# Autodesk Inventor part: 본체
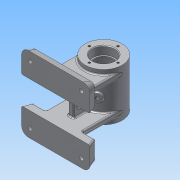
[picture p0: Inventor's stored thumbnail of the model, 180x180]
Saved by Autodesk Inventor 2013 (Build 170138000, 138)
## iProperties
Created: 2016-07
Part Number: 본체
Material: 알루미늄 6061
Document SubType Name: Modeling
Designer: Administrator
Density: 2.71 g/cm^3
Mass: 499.721 g
Surface Area: 539.152 cm^2
Volume: 184.399 cm^3
Author: Administrator
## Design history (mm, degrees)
sketch "스케치1"
  geometry: C1 r 27 at (0, 0); 1 further point
  constraints: 1 centre point, 1 coincident
  dimensions: "d0" = 54 diameter of C1
extrude "돌출1" new body sketch "스케치1" stored distance "d1" = 70; taper "d2" = 0 deg
node "작업 평면1"
node "작업 평면2"
sketch "스케치7"
  geometry: L1 (-40, 45)-(-50, 45); L2 (40, 45)-(50, 45); L3 (-27, -35)-(-27, 35) reference; L4 (27, -35)-(27, 35) reference; L5 (-40, 45)-(-40, 55); L6 (40, 45)-(40, 55); L7 (-40, 55)-(40, 55); L8 (-50, 45)-(-50, 20); L9 (-50, 20)-(50, 20); L10 (50, 20)-(50, 45); A1 r 10 centre (40, 45) between (50, 45) and (40, 55); A2 r 10 centre (-40, 45) between (-40, 55) and (-50, 45); 1 further point
  constraints: 16 end point, 4 point on circle, 3 parallel, 2 centre point, 2 tangent, 1 collinear, 1 horizontal, 1 perpendicular
  dimensions: "d51" = 20 diameter of A1; "d52" = 20 diameter of A2; "d53" = 50 horizontal distance of point (0, 0) L1.end; "d54" = 50 horizontal distance of point (0, 0) L2.end; "d55" = 55 vertical distance of point (0, 0) L5.end; "d56" = 55 vertical distance of point (0, 0) L6.end; "d57" = 20 distance from line of point (0, 0) L9
extrude "돌출5" join sketch "스케치7" distance "d58" = 12; taper "d59" = -20 deg
sketch "스케치8"
  geometry: L1 (-40, -55)-(40, -55) reference; L2 (-45.632, -45)-(-45.632, -24.368) reference; L3 (-45.632, -24.368)-(45.632, -24.368) reference; L4 (45.632, -24.368)-(45.632, -45) reference; L5 (40, -50.632)-(-40, -50.632) reference; L6 (-50, -20)-(-50, -45) reference; L7 (50, -45)-(50, -20) reference; A1 r 5.632 centre (40, -45) between (40, -50.632) and (45.632, -45) reference; A2 r 5.632 centre (-40, -45) between (-45.632, -45) and (-40, -50.632) reference; 3 further points
  dimensions: "d60" = 12.5 distance from line of L1 point (-37.8, -42.5); "d61" = 12.2 distance from line of L6 point (-37.8, -42.5); "d62" = 12.5 distance from line of L1 point (37.5, -42.5); "d63" = 12.5 distance from line of L7 point (37.5, -42.5)
hole "구멍2" sketch "스케치8" at (-37.8, -42.5), (37.5, -42.5) diameter "d64" = 6; stored, may be unused: countersink angle "d68" = 90 deg, drill point angle "d70" = 118 deg; dims "d65" = 6, "d66" = 10, "d67" = 4, "d69" = 8
sketch "스케치9"
  geometry: L1 (27, -35)-(-27, -35) reference; L2 (-27, -35)-(-27, 35) reference; L3 (-27, 35)-(27, 35) reference; L4 (27, 35)-(27, -35) reference; L5 (-70, 55)-(-58, 50.632) reference; L6 (-58, 50.632)-(-58, 24.368) reference; L7 (-58, 24.368)-(-70, 20) reference; L8 (-70, 20)-(-70, 55) reference; L9 (-58, 24.368)-(-58, 20); L10 (-58, 20)-(-70, 20); 1 further point
  constraints: 4 end point, 1 parallel, 1 perpendicular
extrude "돌출6" join sketch "스케치9" stored distance "d71" = 12; taper "d72" = 0 deg
sketch "스케치10"
  geometry: L1 (-45.632, -20)-(45.632, -20) reference; L2 (-27, -20)-(27, -20); L3 (27, -20)-(27, -28); L4 (27, -28)-(-27, -28); L5 (-27, -28)-(-27, -20); 3 further points
  constraints: 8 end point, 2 midpoint, 2 parallel, 1 coincident, 1 horizontal, 1 perpendicular, 1 point on line
  dimensions: "d73" = 54 distance of L3.end L4.end; "d74" = 8 distance of L2.end L3.end
extrude "돌출7" join sketch "스케치10" stored distance "d75" = 12; taper "d76" = 0 deg
fillet "모깎기6" dims "d77" = 2
fillet "모깎기7" dims "d78" = 2
fillet "모깎기8" dims "d79" = 2
fillet "모깎기9" dims "d80" = 2
sketch "스케치11"
  geometry: L1 (27, 35)-(27, -35) reference; L2 (27, -35)-(-27, -35) reference; L3 (-27, -35)-(-27, -28) reference; L4 (-27, -28)-(-56, -28) reference; L5 (-58, -30)-(-58, -49.232) reference; L6 (-59.316, -51.111)-(-70, -55) reference; L7 (-70, -55)-(-70, -20) reference; L8 (-70, -20)-(-27, -20) reference; L9 (-27, -20)-(-27, 20) reference; L10 (-27, 20)-(-70, 20) reference; L11 (-70, 20)-(-70, 55) reference; L12 (-70, 55)-(-59.316, 51.111) reference; L13 (-58, 49.232)-(-58, 30) reference; L14 (-56, 28)-(-27, 28) reference; L15 (-27, 28)-(-27, 35) reference; L16 (-27, 35)-(27, 35) reference; L17 (-48, 9.983)-(-48, -9.983); A1 r 2 centre (-56, -30) between (-56, -28) and (-58, -30) reference; A2 r 2 centre (-60, -49.232) between (-59.316, -51.111) and (-58, -49.232) reference; A3 r 2 centre (-60, 49.232) between (-58, 49.232) and (-59.316, 51.111) reference; A4 r 2 centre (-56, 30) between (-58, 30) and (-56, 28) reference; 1 further point
  constraints: 2 end point, 1 perpendicular
  dimensions: "d81" = 21 distance between parallel lines of L17 L9
feature "리브2" sketch "스케치11" dims "d82" = 1, "d83" = 8, "d84" = 0, "d85" = 0, "d86" = 1, "d87" = 1
sketch "스케치12"
  geometry: L1 (0, 0)-(-40, 0) reference; L2 (-12, 10)-(-8.5, 10); L3 (-28, 10)-(-31.5, 10); L4 (-28, 13.5)-(-12, 13.5); L5 (-28, 6.5)-(-12, 6.5); L6 (2, -22)-(25, -22) reference; L7 (-42, -22)-(-65, -22) reference; A1 r 3.5 centre (-12, 10) between (-12, 6.5) and (-12, 13.5); A2 r 3.5 centre (-28, 10) between (-28, 13.5) and (-28, 6.5); 1 further point
  constraints: 8 end point, 6 point on circle, 4 tangent, 2 centre point, 1 collinear, 1 parallel
  dimensions: "d88" = 7 diameter of A1; "d89" = 7 diameter of A2; "d90" = 11.5 horizontal distance of point (-20, 48) L3.end; "d91" = 11.5 horizontal distance of point (-20, 48) L2.end; "d92" = 32 distance from line of L6 L2.end; "d93" = 32 distance from line of L7 L3.start
extrude "돌출8" cut sketch "스케치12" stored distance "d94" = 12; taper "d95" = 0 deg
fillet "모깎기10" dims "d96" = 2
fillet "모깎기11" dims "d97" = 2
fillet "모깎기12" dims "d98" = 2
fillet "모깎기13" dims "d99" = 2
fillet "모깎기14" dims "d100" = 2
fillet "모깎기15" dims "d101" = 2
sketch "스케치13"
  geometry: L1 (-41.5, 8)-(-41.5, -8) reference; L2 (-34.5, -8)-(-34.5, 8) reference; L3 (-58, 49.232)-(-58, 30) reference; L4 (-56, 28)-(-29, 28) reference; L5 (-27, 30)-(-27, 35) reference; L6 (-27, 35)-(27, 35) reference; L7 (27, 35)-(27, -35) reference; L8 (27, -35)-(-27, -35) reference; L9 (-27, -35)-(-27, -30) reference; L10 (-29, -28)-(-56, -28) reference; L11 (-58, -30)-(-58, -49.232) reference; L12 (-59.316, -51.111)-(-70, -55) reference; L13 (-70, -55)-(-70, -20) reference; L14 (-70, -20)-(-50, -20) reference; L15 (-48, -18)-(-48, 18) reference; L16 (-50, 20)-(-70, 20) reference; L17 (-70, 20)-(-70, 55) reference; L18 (-70, 55)-(-59.316, 51.111) reference; L19 (0, 35)-(0, -35); L20 (16, 35)-(16, 23); L21 (16, 23)-(14, 23); L22 (14, 23)-(14, 21); L23 (14, 21)-(22, 21); L24 (22, 21)-(22, -21); L25 (22, -21)-(14, -21); L26 (14, -21)-(14, -23); L27 (14, -23)-(16, -23); L28 (16, -23)-(16, -35); A1 r 3.5 centre (-38, 8) between (-34.5, 8) and (-41.5, 8) reference; A2 r 3.5 centre (-38, -8) between (-41.5, -8) and (-34.5, -8) reference; A3 r 2 centre (-56, 30) between (-58, 30) and (-56, 28) reference; A4 r 2 centre (-29, 30) between (-29, 28) and (-27, 30) reference; A5 r 2 centre (-29, -30) between (-27, -30) and (-29, -28) reference; A6 r 2 centre (-56, -30) between (-56, -28) and (-58, -30) reference; A7 r 2 centre (-60, -49.232) between (-59.316, -51.111) and (-58, -49.232) reference; A8 r 2 centre (-50, -18) between (-50, -20) and (-48, -18) reference; A9 r 2 centre (-50, 18) between (-48, 18) and (-50, 20) reference; A10 r 2 centre (-60, 49.232) between (-58, 49.232) and (-59.316, 51.111) reference; 1 further point
  constraints: 20 end point, 5 perpendicular, 4 parallel, 2 midpoint, 2 point on line
  dimensions: "d102" = 32 diameter of L20 L19; "d104" = 28 diameter of L22 L19; "d105" = 44 diameter of L24 L19; "d106" = 32 diameter of L28 L19; "d107" = 28 diameter of L26 L19; "d108" = 12 distance between parallel lines of L8 L27; "d109" = 12 distance between parallel lines of L21 L6; "d112" = 2 distance between parallel lines of L23 L21; "d113" = 2 distance between parallel lines of L27 L25
revolve "회전1" sketch "스케치13" stored, may be unused: angle "d114" = 90 deg
chamfer "모따기1" distance "d115" = 1; stored, may be unused: second distance "d116" = 2, angle "d117" = 45 deg
sketch "스케치14"
  geometry: C1 r 27 at (0, 0) reference; 1 further point
  constraints: 1 vertical alignment
  dimensions: "d118" = 21 distance of C1.centre point (0, 21)
hole "구멍3" sketch "스케치14" at (0, 21) diameter "d119" = 3.242; stored, may be unused: countersink angle "d123" = 90 deg, drill point angle "d125" = 118 deg; dims "d120" = 8, "d121" = 10, "d122" = 4, "d124" = 10
node "작업 평면3"
sketch "스케치15"
  geometry: L1 (27, 35)-(-27, 35) reference; L2 (-27, -35)-(27, -35) reference; C1 r 5 at (0, -13); 1 further point
  constraints: 1 centre point, 1 vertical alignment
  dimensions: "d130" = 10 diameter of C1; "d167" = 22 distance from line of L2 C1.centre
extrude "돌출9" join sketch "스케치15" stored distance "d132" = 12; taper "d133" = 0 deg
sketch "스케치16"
  geometry: C1 r 5 at (0, 0) reference; 2 further points
  constraints: 1 coincident
hole "구멍4" sketch "스케치16" at (0, 0) diameter "d134" = 5.188; stored, may be unused: countersink angle "d138" = 90 deg, drill point angle "d140" = 118 deg; dims "d135" = 8, "d136" = 10, "d137" = 4, "d139" = 10
fillet "모깎기16" dims "d141" = 2
sketch "스케치17"
  geometry: L1 (4, -28.373)-(4, -32.5) reference; L2 (2, -34.5)-(-2, -34.5) reference; L3 (-4, -32.5)-(-4, -28.373) reference; L4 (-4, -46)-(-4, -43.5) reference; L5 (-2, -41.5)-(2, -41.5) reference; L6 (4, -43.5)-(4, -46) reference; L7 (2, -48)-(-2, -48) reference; L8 (0, 0)-(0, -21.329); L9 (0, 0)-(15.898, -25.441); C1 r 22 at (0, 0) reference; A1 r 27 centre (0, 0) between (5.586, -26.416) and (-5.586, -26.416) reference; A2 r 2 centre (6, -28.373) between (5.586, -26.416) and (4, -28.373) reference; A3 r 2 centre (2, -32.5) between (2, -34.5) and (4, -32.5) reference; A4 r 2 centre (-2, -32.5) between (-4, -32.5) and (-2, -34.5) reference; A5 r 2 centre (-6, -28.373) between (-4, -28.373) and (-5.586, -26.416) reference; A6 r 2 centre (-2, -46) between (-4, -46) and (-2, -48) reference; A7 r 2 centre (-2, -43.5) between (-2, -41.5) and (-4, -43.5) reference; A8 r 2 centre (2, -43.5) between (4, -43.5) and (2, -41.5) reference; A9 r 2 centre (2, -46) between (2, -48) and (4, -46) reference; 1 further point
  constraints: 4 end point, 1 perpendicular
  dimensions: "d142" = 30 distance of L8.start L9.end; "d143" = 32 deg angle of L9 L8
  node "절단 모서리 투영6"
node "작업 평면4"
sketch "스케치18"
  geometry: C1 r 6 at (0, 0); 1 further point
  constraints: 1 centre point, 1 coincident
  dimensions: "d144" = 12 diameter of C1
extrude "돌출10" join sketch "스케치18" stored distance "d145" = 12; taper "d146" = 0 deg
sketch "스케치19"
  geometry: C1 r 6 at (0, 0) reference; 1 further point
  constraints: 1 coincident
hole "구멍5" sketch "스케치19" at (0, 0) diameter "d147" = 5.188; stored, may be unused: countersink angle "d151" = 90 deg, drill point angle "d153" = 118 deg; dims "d148" = 8, "d149" = 10, "d150" = 4, "d152" = 20
fillet "모깎기17" dims "d154" = 3
fillet "모깎기18" dims "d155" = 0.3
node "작업 평면5"
fillet "모깎기19" dims "d161" = 2
node "작업 평면6"
sketch "스케치21"
  geometry: L1 (-27, -35)-(27, -35) reference; L2 (-27, -35)-(-27, 35) reference; 2 further points
  constraints: 1 other
  dimensions: "d163" = 35 distance from line of L1 point (0, 0); "d164" = 27 distance from line of L2 point (0, 0)
feature "엠보싱2" sketch "스케치21" dims "d165" = 0.5, "d166" = 0
node "솔리드1"
mirror "대칭2"
mirror "대칭3"
pattern_circular "원형 패턴1" dims angle "d127" = 360 deg
mirror "대칭4"
node "절단 모서리 투영2"
node "절단 모서리 투영3"
node "절단 모서리 투영4"
node "절단 모서리 투영5"
other parameters: "d3" = 55, "d156" = 27, "d162" = -27
